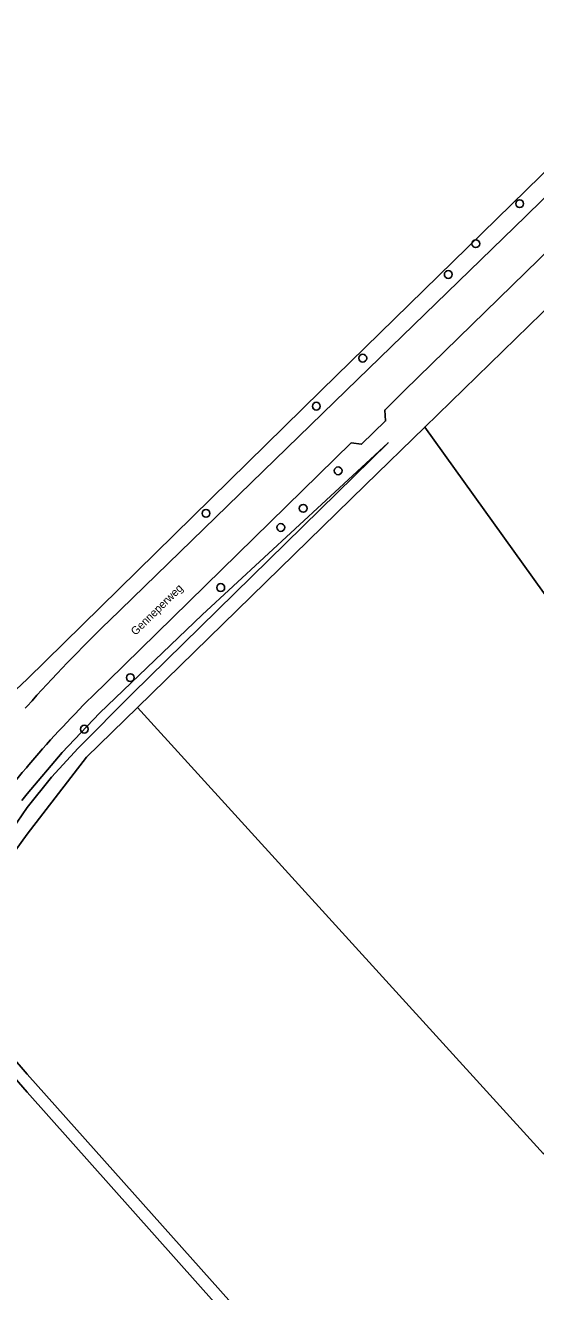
# Model space of a CAD drawing. Extents: x 160203 to 161530, y 379528 to 381797.
# Drawn here: x 160499.8 to 160563.5, y 380137.4 to 380295.6 of the extents above; entities that cross this region are included whole.
import ezdxf

# ---------------------------------------------------------------- set-up
doc = ezdxf.new("R2010")
doc.units = 0
for name, color, linetype in [('IMGEO_Boom', 7, 'Continuous'), ('IMGEO_Bouwland', 7, 'Continuous'), ('IMGEO_Grasland_agrarisch', 7, 'Continuous'), ('IMGEO_Grasland_overig', 7, 'Continuous'), ('IMGEO_Groenvoorziening', 7, 'Continuous'), ('IMGEO_Hek', 7, 'Continuous'), ('IMGEO_Loofbos', 7, 'Continuous'), ('IMGEO_Openbare_ruimte_label', 7, 'Continuous'), ('IMGEO_Rijbaan_lokaal_open', 7, 'Continuous'), ('IMGEO_Waterloop', 7, 'Continuous')]:
    doc.layers.add(name, color=color, linetype=linetype)

msp = doc.modelspace()

# ---------------------------------------------------------------- linework, layer by layer
at = {"layer": 'IMGEO_Boom'}
for centre in [(160561.53, 380273.36), (160556.05, 380268.36), (160552.61, 380264.52), (160541.93, 380254.06), (160536.13, 380248.06), (160538.85, 380239.99), (160534.49, 380235.3), (160522.35, 380234.67), (160531.69, 380232.91), (160524.19, 380225.4), (160512.9, 380214.15), (160507.15, 380207.71)]:
    msp.add_circle(centre, 0.489, dxfattribs=at)
at = {"layer": 'IMGEO_Bouwland'}
msp.add_lwpolyline([(160529.11, 380129.66), (160500, 380162.35), (160492.95, 380170.48), (160489.77, 380174.54), (160486.32, 380173.3), (160457.26, 380127.95), (160449.65, 380116.07), (160442.2, 380102.92)], dxfattribs=at)
at = {"layer": 'IMGEO_Grasland_agrarisch'}
msp.add_lwpolyline([(160488.28, 380202.97), (160500, 380213.96), (160536.75, 380250), (160569.66, 380282.2), (160629.02, 380340.26), (160630.62, 380341.83), (160648.01, 380358.08), (160657.08, 380367.01), (160675.12, 380384.28)], dxfattribs=at)
at = {"layer": 'IMGEO_Grasland_overig'}
msp.add_lwpolyline([(160593.42, 380174.38), (160565.04, 380214.84), (160569.39, 380217.98), (160549.68, 380245.45), (160542.25, 380238.2), (160513.81, 380210.43), (160564.5, 380154.67)], close=True, dxfattribs=at)
msp.add_lwpolyline([(160659.2, 380084.56), (160617.93, 380140.45), (160601.91, 380162.6), (160594.24, 380173.22), (160593.42, 380174.38), (160564.5, 380154.67), (160513.81, 380210.43), (160507.44, 380204.22), (160500, 380194.58), (160496.44, 380189.66), (160493.08, 380184.15), (160491.35, 380180.94), (160490.5, 380178.18), (160491.03, 380175.47), (160489.77, 380174.54), (160492.95, 380170.48), (160494.11, 380171.46), (160500, 380164.6), (160528.98, 380132.14)], dxfattribs=at)
at = {"layer": 'IMGEO_Groenvoorziening'}
for points in [[(160510.21, 380221.21), (160539.87, 380250), (160562.31, 380271.78), (160566.52, 380275.92), (160630.06, 380337.97), (160629.86, 380339.44), (160632.26, 380342.12), (160634.26, 380342.09), (160702.25, 380407.88), (160701.7, 380410.43), (160707.02, 380415.54), (160709.26, 380414.82), (160745.87, 380450.92), (160745.68, 380453.36), (160747.47, 380455.4), (160750.16, 380455.12), (160780.47, 380484.65)], [(160675.12, 380384.28), (160657.08, 380367.01), (160648.01, 380358.08), (160630.62, 380341.83), (160629.02, 380340.26), (160569.66, 380282.2), (160536.75, 380250), (160500, 380213.96), (160488.28, 380202.97), (160488.56, 380200.2), (160488.41, 380197.73), (160488.15, 380196.7), (160486.93, 380194.92), (160473.38, 380174.06), (160474.26, 380173.1), (160482.9, 380187.81)], [(160542.25, 380238.2), (160549.68, 380245.45), (160570.8, 380266.01), (160573.36, 380269.26), (160570.68, 380272.95), (160547.14, 380250), (160544.67, 380247.58), (160544.77, 380246.23), (160541.79, 380243.31), (160540.5, 380243.5), (160508.08, 380211.76)], [(160499.35, 380198.81), (160500, 380199.64), (160504.38, 380204.81), (160509.04, 380209.73), (160521.89, 380221.98), (160545.1, 380243.49), (160513.11, 380212.12), (160506.37, 380205.33), (160503.05, 380201.73), (160500, 380197.91), (160496.87, 380193.33)], [(160489.13, 380178.04), (160491.03, 380175.47), (160490.5, 380178.18), (160491.35, 380180.94), (160493.08, 380184.15), (160496.44, 380189.66), (160500, 380194.58), (160507.44, 380204.22), (160513.81, 380210.43), (160542.25, 380238.2)], [(160499.78, 380210.34), (160500, 380210.58)], [(160500, 380202.99), (160499.91, 380202.88)]]:
    msp.add_lwpolyline(points, dxfattribs=at)
for centre, radius, start, end in [((160661.87, 380065.31), 217.5, 134.2108, 138.0934), ((160603.27, 380115.91), 135.09, 134.8017, 139.861), ((160602.61, 380116.53), 134.18, 139.9428, 150.6966)]:
    msp.add_arc(centre, radius, start, end, dxfattribs=at)
at = {"layer": 'IMGEO_Hek'}
msp.add_lwpolyline([(160542.25, 380238.2), (160513.81, 380210.43)], dxfattribs=at)
at = {"layer": 'IMGEO_Loofbos'}
msp.add_lwpolyline([(160549.68, 380245.45), (160569.39, 380217.98), (160593.46, 380235.35), (160582.63, 380250), (160570.8, 380266.01)], close=True, dxfattribs=at)
at = {"layer": 'IMGEO_Rijbaan_lokaal_open'}
for points in [[(160508.08, 380211.76), (160540.5, 380243.5), (160541.79, 380243.31), (160544.77, 380246.23), (160544.67, 380247.58), (160547.14, 380250), (160570.68, 380272.95), (160575.07, 380277.29), (160633.67, 380334.4), (160634.91, 380335.61), (160699.48, 380398.59), (160757.45, 380455.04), (160785.59, 380482.49), (160789.17, 380485.87), (160789.09, 380486), (160785.49, 380489.98), (160783.87, 380488.23)], [(160780.47, 380484.65), (160750.16, 380455.12), (160747.47, 380455.4), (160745.68, 380453.36), (160745.87, 380450.92), (160709.26, 380414.82), (160707.02, 380415.54), (160701.7, 380410.43), (160702.25, 380407.88), (160634.26, 380342.09), (160632.26, 380342.12), (160629.86, 380339.44), (160630.06, 380337.97), (160566.52, 380275.92), (160562.31, 380271.78), (160539.87, 380250), (160510.21, 380221.21)], [(160500, 380210.58), (160499.78, 380210.34)], [(160499.91, 380202.88), (160500, 380202.99)]]:
    msp.add_lwpolyline(points, dxfattribs=at)
for centre, radius, start, end in [((160661.87, 380065.31), 217.5, 134.2108, 138.0934), ((160603.27, 380115.91), 135.09, 134.8017, 139.861), ((160602.61, 380116.53), 134.18, 139.9428, 150.6966)]:
    msp.add_arc(centre, radius, start, end, dxfattribs=at)
at = {"layer": 'IMGEO_Waterloop'}
msp.add_lwpolyline([(160496.87, 380193.33), (160500, 380197.91), (160503.05, 380201.73), (160506.37, 380205.33), (160513.11, 380212.12), (160545.1, 380243.49), (160521.89, 380221.98), (160509.04, 380209.73), (160504.38, 380204.81), (160500, 380199.64), (160499.35, 380198.81)], dxfattribs=at)
msp.add_lwpolyline([(160531.73, 380131.42), (160531.16, 380131.71), (160529.66, 380131.61), (160528.98, 380132.14), (160500, 380164.6), (160494.11, 380171.46), (160492.95, 380170.48), (160500, 380162.35), (160529.11, 380129.66)], close=True, dxfattribs=at)

# ---------------------------------------------------------------- texts
at = {"layer": 'IMGEO_Openbare_ruimte_label'}
msp.add_text('Genneperweg', height=1, rotation=44.2707, dxfattribs=at).set_placement((160513.54, 380219.36))

doc.saveas('drawing.dxf')
